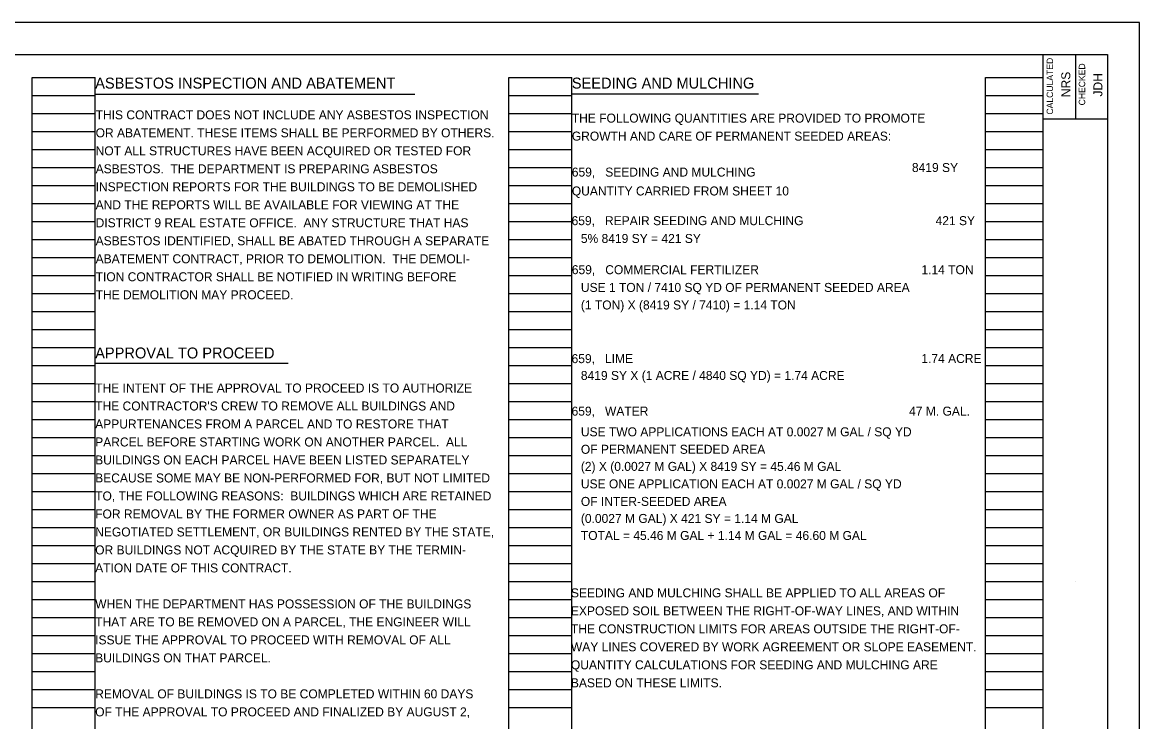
# Model space of a CAD drawing. Extents: x 0 to 34, y 0 to 22.
# Drawn here: x 16.61 to 34, y 11.12 to 22 of the extents above; entities that cross this region are included whole.
import ezdxf

# ---------------------------------------------------------------- set-up
doc = ezdxf.new("R2010")
doc.units = 0
for name, color, linetype in [('Default', 7, 'Continuous'), ('SC_Scratch2', 7, 'Continuous'), ('SH_Border', 7, 'Continuous'), ('SH_Cut_Line', 7, 'Continuous'), ('SH_Data', 7, 'Continuous'), ('SH_Text', 7, 'Continuous'), ('TX_P_1', 7, 'Continuous')]:
    doc.layers.add(name, color=color, linetype=linetype)

msp = doc.modelspace()

# ---------------------------------------------------------------- linework, layer by layer
at = {"layer": 'SC_Scratch2'}
for p, q in [((16.76, 0.98), (16.76, 21.14)), ((16.76, 21.14), (17.74, 21.14)), ((17.74, 0.98), (17.74, 21.14)), ((24.18, 0.98), (24.18, 21.14)), ((24.18, 21.14), (25.16, 21.14)), ((25.16, 0.98), (25.16, 21.14)), ((31.6, 0.98), (31.6, 21.14)), ((31.6, 21.14), (32.5, 21.14)), ((32.5, 0.98), (32.5, 21.14)), ((16.76, 20.86), (17.74, 20.86)), ((24.18, 20.86), (25.16, 20.86)), ((31.6, 20.86), (32.5, 20.86)), ((16.76, 20.58), (17.74, 20.58)), ((24.18, 20.58), (25.16, 20.58)), ((31.6, 20.58), (32.5, 20.58)), ((16.76, 20.3), (17.74, 20.3)), ((24.18, 20.3), (25.16, 20.3)), ((31.6, 20.3), (32.5, 20.3)), ((16.76, 20.02), (17.74, 20.02)), ((24.18, 20.02), (25.16, 20.02)), ((31.6, 20.02), (32.5, 20.02)), ((16.76, 19.74), (17.74, 19.74)), ((24.18, 19.74), (25.16, 19.74)), ((31.6, 19.74), (32.5, 19.74)), ((16.76, 19.46), (17.74, 19.46)), ((24.18, 19.46), (25.16, 19.46)), ((31.6, 19.46), (32.5, 19.46)), ((16.76, 19.18), (17.74, 19.18)), ((24.18, 19.18), (25.16, 19.18)), ((31.6, 19.18), (32.5, 19.18)), ((16.76, 18.9), (17.74, 18.9)), ((24.18, 18.9), (25.16, 18.9)), ((31.6, 18.9), (32.5, 18.9)), ((16.76, 18.62), (17.74, 18.62)), ((24.18, 18.62), (25.16, 18.62)), ((31.6, 18.62), (32.5, 18.62)), ((16.76, 18.34), (17.74, 18.34)), ((24.18, 18.34), (25.16, 18.34)), ((31.6, 18.34), (32.5, 18.34)), ((16.76, 18.06), (17.74, 18.06)), ((24.18, 18.06), (25.16, 18.06)), ((31.6, 18.06), (32.5, 18.06)), ((16.76, 17.78), (17.74, 17.78)), ((24.18, 17.78), (25.16, 17.78)), ((31.6, 17.78), (32.5, 17.78)), ((16.76, 17.5), (17.74, 17.5)), ((24.18, 17.5), (25.16, 17.5)), ((31.6, 17.5), (32.5, 17.5)), ((16.76, 17.22), (17.74, 17.22)), ((24.18, 17.22), (25.16, 17.22)), ((31.6, 17.22), (32.5, 17.22)), ((16.76, 16.94), (17.74, 16.94)), ((24.18, 16.94), (25.16, 16.94)), ((31.6, 16.94), (32.5, 16.94)), ((16.76, 16.66), (17.74, 16.66)), ((24.18, 16.66), (25.16, 16.66)), ((31.6, 16.66), (32.5, 16.66)), ((16.76, 16.38), (17.74, 16.38)), ((24.18, 16.38), (25.16, 16.38)), ((31.6, 16.38), (32.5, 16.38)), ((16.76, 16.1), (17.74, 16.1)), ((24.18, 16.1), (25.16, 16.1)), ((31.6, 16.1), (32.5, 16.1)), ((16.76, 15.82), (17.74, 15.82)), ((24.18, 15.82), (25.16, 15.82)), ((31.6, 15.82), (32.5, 15.82)), ((16.76, 15.54), (17.74, 15.54)), ((24.18, 15.54), (25.16, 15.54)), ((31.6, 15.54), (32.5, 15.54)), ((16.76, 15.26), (17.74, 15.26)), ((24.18, 15.26), (25.16, 15.26)), ((31.6, 15.26), (32.5, 15.26)), ((16.76, 14.98), (17.74, 14.98)), ((24.18, 14.98), (25.16, 14.98)), ((31.6, 14.98), (32.5, 14.98)), ((16.76, 14.7), (17.74, 14.7)), ((24.18, 14.7), (25.16, 14.7)), ((31.6, 14.7), (32.5, 14.7)), ((16.76, 14.42), (17.74, 14.42)), ((24.18, 14.42), (25.16, 14.42)), ((31.6, 14.42), (32.5, 14.42)), ((16.76, 14.14), (17.74, 14.14)), ((24.18, 14.14), (25.16, 14.14)), ((31.6, 14.14), (32.5, 14.14)), ((16.76, 13.86), (17.74, 13.86)), ((24.18, 13.86), (25.16, 13.86)), ((31.6, 13.86), (32.5, 13.86)), ((16.76, 13.58), (17.74, 13.58)), ((24.18, 13.58), (25.16, 13.58)), ((31.6, 13.58), (32.5, 13.58)), ((16.76, 13.3), (17.74, 13.3)), ((24.18, 13.3), (25.16, 13.3)), ((31.6, 13.3), (32.5, 13.3)), ((16.76, 13.02), (17.74, 13.02)), ((24.18, 13.02), (25.16, 13.02)), ((31.6, 13.02), (32.5, 13.02)), ((16.76, 12.74), (17.74, 12.74)), ((24.18, 12.74), (25.16, 12.74)), ((31.6, 12.74), (32.5, 12.74)), ((16.76, 12.46), (17.74, 12.46)), ((24.18, 12.46), (25.16, 12.46)), ((31.6, 12.46), (32.5, 12.46)), ((16.76, 12.18), (17.74, 12.18)), ((24.18, 12.18), (25.16, 12.18)), ((31.6, 12.18), (32.5, 12.18)), ((16.76, 11.9), (17.74, 11.9)), ((24.18, 11.9), (25.16, 11.9)), ((31.6, 11.9), (32.5, 11.9)), ((16.76, 11.62), (17.74, 11.62)), ((24.18, 11.62), (25.16, 11.62)), ((31.6, 11.62), (32.5, 11.62)), ((16.76, 11.34), (17.74, 11.34)), ((24.18, 11.34), (25.16, 11.34)), ((31.6, 11.34), (32.5, 11.34))]:
    msp.add_line(p, q, dxfattribs=at)
at = {"layer": 'SH_Border'}
for p, q in [((32.5, 0.5), (32.5, 21.5)), ((33, 21.5), (33, 20.5)), ((32.5, 20.5), (33.5, 20.5))]:
    msp.add_line(p, q, dxfattribs=at)
msp.add_lwpolyline([(2, 21.5), (33.5, 21.5), (33.5, 0.5), (2, 0.5)], close=True, dxfattribs=at)
at = {"layer": 'SH_Cut_Line'}
msp.add_lwpolyline([(0, 0), (34, 0), (34, 22), (0, 22)], close=True, dxfattribs=at)
at = {"layer": 'SH_Data'}
for p, q in [((32.92, 21.004), (32.92, 21.004)), ((33.42, 21.004), (33.42, 21.004)), ((33, 13.292), (33, 13.292))]:
    msp.add_line(p, q, dxfattribs=at)
at = {"layer": 'TX_P_1'}
for p, q in [((17.747, 20.883), (22.717, 20.883)), ((25.167, 20.889), (28.067, 20.889)), ((17.747, 16.698), (20.744, 16.698))]:
    msp.add_line(p, q, dxfattribs=at)

# ---------------------------------------------------------------- texts
at = {"layer": 'Default'}
for s, p in [('8419 SY', (30.455, 19.671)), ('421 SY', (30.823, 18.844)), ('5% 8419 SY = 421 SY', (25.301, 18.567)), ('1.14 TON', (30.603, 18.081)), ('USE 1 TON / 7410 SQ YD OF PERMANENT SEEDED AREA', (25.301, 17.805)), ('(1 TON) X (8419 SY / 7410) = 1.14 TON', (25.301, 17.532)), ('1.74 ACRE', (30.602, 16.699)), ('8419 SY X (1 ACRE / 4840 SQ YD) = 1.74 ACRE', (25.301, 16.435)), ('47 M. GAL.', (30.411, 15.88)), ('USE TWO APPLICATIONS EACH AT 0.0027 M GAL / SQ YD ', (25.301, 15.558)), ('OF PERMANENT SEEDED AREA', (25.301, 15.286)), ('(2) X (0.0027 M GAL) X 8419 SY = 45.46 M GAL', (25.301, 15.02)), ('USE ONE APPLICATION EACH AT 0.0027 M GAL / SQ YD ', (25.301, 14.748)), ('OF INTER-SEEDED AREA', (25.301, 14.475)), ('(0.0027 M GAL) X 421 SY = 1.14 M GAL', (25.301, 14.21)), ('TOTAL = 45.46 M GAL + 1.14 M GAL = 46.60 M GAL', (25.301, 13.945))]:
    msp.add_text(s, height=0.14, dxfattribs=at).set_placement(p)
at = {"layer": 'SH_Data'}
for s, p in [('CALCULATED', (32.652, 20.565)), ('CHECKED', (33.152, 20.708))]:
    msp.add_text(s, height=0.1, rotation=90, dxfattribs=at).set_placement(p)
at = {"layer": 'SH_Text'}
for s, p in [('NRS', (32.92, 20.836)), ('JDH', (33.42, 20.846))]:
    msp.add_text(s, height=0.14, rotation=90, dxfattribs=at).set_placement(p)
at = {"layer": 'TX_P_1'}
for s, height, p in [('ASBESTOS INSPECTION AND ABATEMENT', 0.17, (17.74, 20.97)), ('SEEDING AND MULCHING', 0.17, (25.16, 20.97)), ('THIS CONTRACT DOES NOT INCLUDE ANY ASBESTOS INSPECTION', 0.14, (17.747, 20.491)), ('THE FOLLOWING QUANTITIES ARE PROVIDED TO PROMOTE ', 0.14, (25.16, 20.44)), ('OR ABATEMENT. THESE ITEMS SHALL BE PERFORMED BY OTHERS.  ', 0.14, (17.747, 20.211)), ('GROWTH AND CARE OF PERMANENT SEEDED AREAS:', 0.14, (25.16, 20.16)), ('NOT ALL STRUCTURES HAVE BEEN ACQUIRED OR TESTED FOR ', 0.14, (17.747, 19.931)), ('ASBESTOS.  THE DEPARTMENT IS PREPARING ASBESTOS ', 0.14, (17.747, 19.651)), ('659,   SEEDING AND MULCHING                           ', 0.14, (25.16, 19.6)), ('INSPECTION REPORTS FOR THE BUILDINGS TO BE DEMOLISHED ', 0.14, (17.747, 19.371)), ('QUANTITY CARRIED FROM SHEET 10', 0.14, (25.16, 19.306)), ('AND THE REPORTS WILL BE AVAILABLE FOR VIEWING AT THE ', 0.14, (17.747, 19.091)), ('659,   REPAIR SEEDING AND MULCHING                     ', 0.14, (25.156, 18.844)), ('DISTRICT 9 REAL ESTATE OFFICE.  ANY STRUCTURE THAT HAS ', 0.14, (17.747, 18.811)), ('ASBESTOS IDENTIFIED, SHALL BE ABATED THROUGH A SEPARATE ', 0.14, (17.747, 18.531)), ('ABATEMENT CONTRACT, PRIOR TO DEMOLITION.  THE DEMOLI-', 0.14, (17.747, 18.251)), ('TION CONTRACTOR SHALL BE NOTIFIED IN WRITING BEFORE ', 0.14, (17.747, 17.971)), ('659,   COMMERCIAL FERTILIZER                           ', 0.14, (25.16, 18.081)), ('THE DEMOLITION MAY PROCEED.', 0.14, (17.747, 17.691)), ('APPROVAL TO PROCEED', 0.17, (17.74, 16.77)), ('659,   LIME                                              ', 0.14, (25.156, 16.697)), ('THE INTENT OF THE APPROVAL TO PROCEED IS TO AUTHORIZE ', 0.14, (17.74, 16.24)), ("THE CONTRACTOR'S CREW TO REMOVE ALL BUILDINGS AND ", 0.14, (17.74, 15.96)), ('659,   WATER                                          ', 0.14, (25.156, 15.88)), ('APPURTENANCES FROM A PARCEL AND TO RESTORE THAT ', 0.14, (17.74, 15.68)), ('PARCEL BEFORE STARTING WORK ON ANOTHER PARCEL.  ALL ', 0.14, (17.74, 15.4)), ('BUILDINGS ON EACH PARCEL HAVE BEEN LISTED SEPARATELY ', 0.14, (17.74, 15.12)), ('BECAUSE SOME MAY BE NON-PERFORMED FOR, BUT NOT LIMITED ', 0.14, (17.74, 14.84)), ('TO, THE FOLLOWING REASONS:  BUILDINGS WHICH ARE RETAINED ', 0.14, (17.74, 14.56)), ('FOR REMOVAL BY THE FORMER OWNER AS PART OF THE ', 0.14, (17.74, 14.28)), ('NEGOTIATED SETTLEMENT, OR BUILDINGS RENTED BY THE STATE,', 0.14, (17.74, 14)), ('OR BUILDINGS NOT ACQUIRED BY THE STATE BY THE TERMIN-', 0.14, (17.74, 13.72)), ('ATION DATE OF THIS CONTRACT.', 0.14, (17.74, 13.44)), ('SEEDING AND MULCHING SHALL BE APPLIED TO ALL AREAS OF ', 0.14, (25.146, 13.052)), ('WHEN THE DEPARTMENT HAS POSSESSION OF THE BUILDINGS ', 0.14, (17.74, 12.88)), ('EXPOSED SOIL BETWEEN THE RIGHT-OF-WAY LINES, AND WITHIN ', 0.14, (25.146, 12.772)), ('THAT ARE TO BE REMOVED ON A PARCEL, THE ENGINEER WILL ', 0.14, (17.74, 12.6)), ('THE CONSTRUCTION LIMITS FOR AREAS OUTSIDE THE RIGHT-OF-', 0.14, (25.146, 12.492)), ('ISSUE THE APPROVAL TO PROCEED WITH REMOVAL OF ALL ', 0.14, (17.74, 12.32)), ('WAY LINES COVERED BY WORK AGREEMENT OR SLOPE EASEMENT.  ', 0.14, (25.146, 12.212)), ('BUILDINGS ON THAT PARCEL.', 0.14, (17.74, 12.04)), ('QUANTITY CALCULATIONS FOR SEEDING AND MULCHING ARE ', 0.14, (25.146, 11.932)), ('BASED ON THESE LIMITS.', 0.14, (25.146, 11.652)), ('REMOVAL OF BUILDINGS IS TO BE COMPLETED WITHIN 60 DAYS ', 0.14, (17.74, 11.48)), ('OF THE APPROVAL TO PROCEED AND FINALIZED BY AUGUST 2, ', 0.14, (17.74, 11.2))]:
    msp.add_text(s, height=height, dxfattribs=at).set_placement(p)

doc.saveas('drawing.dxf')
